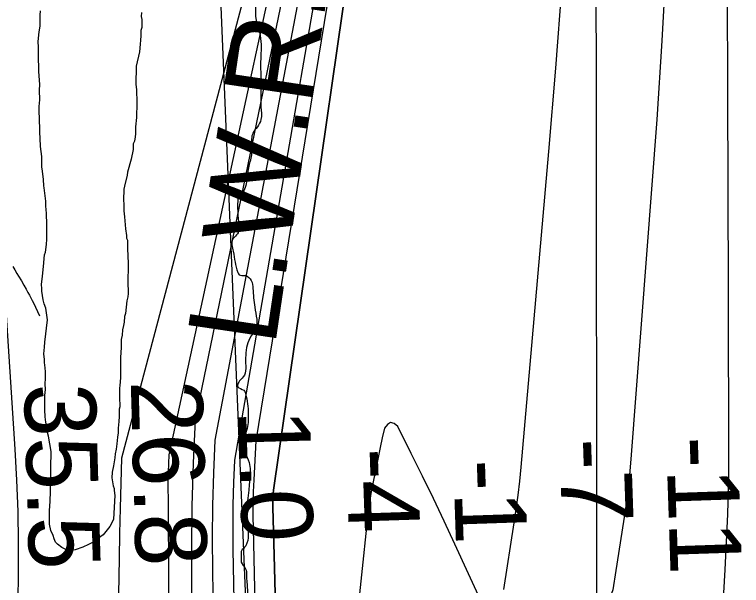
# Model space of a CAD drawing. Extents: x 3313447 to 3351316, y 703786 to 729172.
# Drawn here: x 3322283 to 3322964, y 725253 to 725788 of the extents above; entities that cross this region are included whole.
import ezdxf

# ---------------------------------------------------------------- set-up
doc = ezdxf.new("R2010")
doc.units = 0
for name, color, linetype in [('V-GRID-MAJR', 7, 'Continuous'), ('V-RIVR-EDGE', 7, 'Continuous'), ('V-RIVR-RANG', 7, 'Continuous'), ('V-ROAD-CNTR', 7, 'Continuous'), ('V-RRAP-FSHR', 7, 'Continuous'), ('V-SITE-VEGE', 7, 'Continuous'), ('V-TOPO-DPTH', 7, 'Continuous'), ('V-TOPO-MAJR', 7, 'Continuous'), ('V-TOPO-MINR', 7, 'Continuous'), ('V-TOPO-WATR', 7, 'Continuous'), ('V-TOPO-WATR-IDEN', 7, 'Continuous')]:
    doc.layers.add(name, color=color, linetype=linetype)

msp = doc.modelspace()

# ---------------------------------------------------------------- linework, layer by layer
at = {"layer": 'V-GRID-MAJR'}
msp.add_spline([(3322840.097, 715233.372), (3322833.044, 721295.0380000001), (3322825.991, 727356.734), (3322825.989, 727358.642)], degree=3, dxfattribs=at)
at = {"layer": 'V-RIVR-EDGE'}
msp.add_spline([(3322621.39367418, 727358.3440878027), (3322620.017507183, 727344.96628995), (3322617.494746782, 727330.465586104), (3322616.640161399, 727320.1055978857), (3322620.7439808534, 727303.5160881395), (3322619.4605654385, 727287.3543835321), (3322619.8156031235, 727263.3134304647), (3322623.0412646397, 727226.8308575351), (3322631.523999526, 727137.2813263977), (3322631.0326509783, 727106.1962372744), (3322631.78167231, 727073.8646289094), (3322633.7710635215, 727040.2865013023), (3322632.837561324, 726998.0114360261), (3322629.425369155, 726959.0583722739), (3322631.0146273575, 726931.2840108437), (3322631.385038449, 726913.4602805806), (3322630.5058556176, 726893.1527358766), (3322630.0257809, 726866.6269434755), (3322631.585317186, 726826.832617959), (3322632.7324217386, 726787.8682803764), (3322631.8306912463, 726758.4421422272), (3322628.8381050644, 726721.5604611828), (3322624.2439619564, 726707.4793633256), (3322616.3124439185, 726684.7023526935), (3322612.969944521, 726673.9340323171), (3322610.4502588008, 726660.6767730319), (3322609.184266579, 726651.5612542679), (3322610.3508441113, 726620.4720655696), (3322608.515611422, 726548.7708621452), (3322601.30954216, 726484.1291681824), (3322595.0103278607, 726450.9860199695), (3322590.8245169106, 726434.4170080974), (3322587.496366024, 726429.4514290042), (3322580.435831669, 726423.666110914), (3322577.5242120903, 726419.5284699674), (3322577.102556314, 726416.62812422), (3322577.0892326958, 726411.2398644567), (3322579.968055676, 726402.1140967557), (3322579.100146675, 726386.3658487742), (3322569.100320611, 726365.2518886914), (3322564.5051526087, 726350.756309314), (3322557.812979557, 726326.3182979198), (3322551.9425952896, 726298.9768660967), (3322541.9161219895, 726267.0863864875), (3322531.475167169, 726235.1969317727), (3322515.200724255, 726190.8873799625), (3322507.239484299, 726156.0904052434), (3322503.4199848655, 726120.0397370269), (3322504.1444087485, 726077.7605721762), (3322502.421914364, 726051.6523359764), (3322495.2886125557, 726016.43882995), (3322494.4360769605, 726006.9078047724), (3322495.1943223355, 725978.3065300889), (3322498.8201168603, 725936.0201909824), (3322500.818732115, 725906.1723970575), (3322498.3205691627, 725901.6192496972), (3322497.879440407, 725890.843755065), (3322497.4096146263, 725868.4627778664), (3322499.048067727, 725860.5835294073), (3322502.748679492, 725848.5543412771), (3322506.036859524, 725837.3551410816), (3322506.012262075, 725827.4075845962), (3322505.579332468, 725819.9479421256), (3322505.98049037, 725814.5586574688), (3322509.2748197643, 725805.8463463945), (3322509.26252104, 725800.8725681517), (3322508.4140850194, 725792.999469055), (3322508.8060188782, 725783.8798507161), (3322512.0900993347, 725771.0227244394), (3322513.7193283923, 725759.413142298), (3322513.2659009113, 725743.6638694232), (3322513.6322124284, 725724.1822130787), (3322513.5748183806, 725700.971247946), (3322513.546121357, 725689.3657653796), (3322510.2128460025, 725682.3277786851), (3322506.053682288, 725676.5352863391), (3322504.79691411, 725671.1501012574), (3322504.7641175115, 725657.88669261), (3322502.246481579, 725645.4583963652), (3322500.142302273, 725632.6145937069), (3322495.5512338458, 725619.7769404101), (3322492.6426889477, 725616.8827440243), (3322491.8045018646, 725613.1544601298), (3322492.567871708, 725586.6255930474), (3322492.145191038, 725583.3107657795), (3322488.8190899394, 725579.1741497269), (3322487.15603939, 725577.1058417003), (3322487.5428487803, 725565.9138157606), (3322492.0529506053, 725546.0074289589), (3322493.291270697, 725543.9319466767), (3322498.677480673, 725543.0896600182), (3322504.468948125, 725538.5160147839), (3322506.1084261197, 725531.0512478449), (3322507.7233066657, 725513.6389244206), (3322508.084493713, 725492.0848604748), (3322504.3408364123, 725486.7058247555), (3322500.588979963, 725478.0109368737), (3322499.2973653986, 725458.5333801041), (3322498.03239807, 725449.83234286), (3322493.4597777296, 725444.4553569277), (3322492.2112087, 725442.3860240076), (3322491.7885280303, 725439.0711967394), (3322497.5830701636, 725435.7409960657), (3322499.2327970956, 725432.421044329), (3322501.673566, 725413.7632265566), (3322499.976693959, 725398.0170283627), (3322496.643418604, 725390.9790416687), (3322495.809331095, 725388.9086838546), (3322496.2156134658, 725385.5918067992), (3322498.682004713, 725377.2960270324), (3322502.389790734, 725368.1682095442), (3322503.179807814, 725352.4158619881), (3322500.5924791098, 725311.8028223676), (3322499.2957400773, 725290.2528579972), (3322496.8016767, 725287.3576367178), (3322495.555157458, 725286.1172668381), (3322495.126327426, 725280.3155504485), (3322495.113003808, 725274.9272906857), (3322499.2424456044, 725268.6998189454), (3322500.0560352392, 725262.4805463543), (3322500.852201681, 725249.21508792), (3322500.418247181, 725241.3409639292), (3322499.165578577, 725237.6137049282), (3322496.6684405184, 725233.475039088), (3322496.24063538, 725228.0878042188), (3322496.218087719, 725218.9692107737), (3322496.2088636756, 725215.2388770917), (3322492.455982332, 725206.12950769), (3322492.847916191, 725197.0098893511), (3322495.686768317, 725171.7193423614), (3322501.0135344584, 725146.8371275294), (3322500.974588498, 725131.0868297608), (3322500.922318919, 725109.9482722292), (3322499.2541439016, 725105.8075566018), (3322497.175586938, 725103.325791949), (3322497.168412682, 725100.4244213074), (3322499.1947000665, 725081.7676284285), (3322501.214838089, 725060.6239464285), (3322504.05778979, 725036.9913255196), (3322501.9700087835, 725030.7792271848), (3322500.710165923, 725024.1505975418), (3322501.1041495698, 725015.8599422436), (3322506.0359071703, 724998.8539011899), (3322509.70167255, 724972.7323413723), (3322511.7084869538, 724946.2003996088), (3322509.619681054, 724939.573819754), (3322507.546248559, 724939.1644627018), (3322507.120493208, 724934.6061908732), (3322506.6885884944, 724927.561029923), (3322506.6783395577, 724923.4162147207), (3322510.801631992, 724914.701853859), (3322512.017404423, 724903.5077781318), (3322512.409338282, 724894.3881597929), (3322511.1546198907, 724889.8319377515), (3322507.404813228, 724881.9660129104), (3322507.3966140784, 724878.6501607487), (3322507.798796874, 724873.6753576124), (3322511.099275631, 724867.4499356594), (3322513.565666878, 724859.1541558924), (3322513.1399115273, 724854.5958840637), (3322510.643798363, 724850.8716997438), (3322513.5349200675, 724846.7197102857), (3322517.228357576, 724831.7891515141), (3322520.1266535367, 724830.5385326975), (3322525.070709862, 724818.5062698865), (3322527.088798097, 724796.533624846), (3322526.2598350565, 724796.5356746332), (3322525.8422788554, 724795.2932549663), (3322517.139191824, 724795.729259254), (3322516.7144613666, 724791.5854689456), (3322517.1248433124, 724789.9265179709), (3322525.409349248, 724787.8336124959), (3322527.474582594, 724784.9271173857), (3322529.4895961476, 724761.7110277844), (3322532.3274233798, 724736.0059992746), (3322531.0511822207, 724722.7456653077), (3322528.140587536, 724719.0225058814), (3322527.714832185, 724714.4642340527), (3322529.773916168, 724709.0708498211), (3322531.8422241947, 724707.4077992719), (3322531.8350499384, 724704.5064286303), (3322529.70524829, 724681.3005879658), (3322528.0309239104, 724674.672983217), (3322523.0366477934, 724666.395651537), (3322520.542584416, 724663.5004302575), (3322520.523111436, 724655.6252813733), (3322520.0686590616, 724639.4615269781)], degree=3, dxfattribs=at)
at = {"layer": 'V-ROAD-CNTR'}
msp.add_lwpolyline([(3322281.0474005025, 725551.4958699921), (3322283.061396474, 725548.38187622), (3322285.027392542, 725545.229882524), (3322286.537389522, 725542.7398875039), (3322289.23338413, 725538.1728966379), (3322291.5473795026, 725534.1279047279), (3322293.527375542, 725530.5709118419), (3322295.22837214, 725527.442918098), (3322296.702369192, 725524.6749236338), (3322299.192364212, 725519.879933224), (3322301.030360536, 725516.2379405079), (3322302.392357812, 725513.4819460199), (3322304.381353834, 725509.372954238), (3322306.3043499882, 725505.297962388)], dxfattribs=at)
at = {"layer": 'V-RRAP-FSHR'}
msp.add_lwpolyline([(3322431.258565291, 727358.0675405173), (3322429.6418011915, 726904.7021123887), (3322510.566473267, 724962.8540465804), (3322576.3154653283, 723396.5395491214), (3322621.0663133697, 721565.6439314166)], dxfattribs=at)
at = {"layer": 'V-SITE-VEGE'}
for points in [[(3322314.583, 725392.7930000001), (3322313.387, 725397.343), (3322313.018, 725401.888), (3322312.232, 725406.0210000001), (3322311.452, 725410.981), (3322311.1040000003, 725417.59), (3322311.228, 725430.791), (3322311.6950000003, 725436.5650000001), (3322311.335, 725441.932), (3322311.792, 725446.88), (3322311.8510000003, 725453.069), (3322311.472, 725456.789), (3322310.696, 725461.747), (3322310.723, 725464.637), (3322310.36, 725470.004), (3322310.8310000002, 725476.189), (3322311.286, 725480.726), (3322313.549, 725501.75), (3322312.787, 725508.359), (3322311.9990000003, 725512.4940000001), (3322310.389, 725516.637), (3322309.596, 725520.359), (3322308.437, 725528.622), (3322308.4620000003, 725531.098), (3322308.085, 725534.8150000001), (3322308.984, 725542.649), (3322309.893, 725551.72), (3322310.821, 725562.441), (3322311.669, 725564.909), (3322312.5640000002, 725572.329), (3322313.025, 725577.277), (3322313.156, 725591.305), (3322312.832, 725600.8), (3322312.463, 725605.3420000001), (3322312.074, 725607.822), (3322312.1210000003, 725612.775), (3322310.59, 725625.171), (3322310.194, 725627.238), (3322309.836, 725633.017), (3322309.0840000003, 725640.867), (3322308.298, 725645.002), (3322308.3880000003, 725654.49), (3322307.61, 725659.451), (3322307.239, 725663.993), (3322306.901, 725671.837), (3322306.539, 725677.205), (3322306.27, 725692.4770000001), (3322305.875, 725694.5430000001), (3322305.9450000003, 725701.559), (3322306.416, 725707.7440000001), (3322306.088, 725716.827), (3322306.551, 725722.187), (3322305.427, 725734.166), (3322305.478, 725739.529), (3322305.115, 725744.897), (3322305.228, 725756.866), (3322304.865, 725762.234), (3322305.7770000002, 725771.304), (3322306.653, 725776.66), (3322306.75, 725786.9770000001), (3322307.202, 725791.098)], [(3322401.734, 725789.335), (3322401.244, 725785.671), (3322402.041, 725782.775), (3322401.969, 725775.345), (3322401.117, 725772.4670000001), (3322401.0700000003, 725767.515), (3322400.62, 725763.393), (3322400.583, 725759.68), (3322399.694, 725752.671), (3322396.6750000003, 725739.083), (3322396.515, 725722.162), (3322396.882, 725717.208), (3322397.177, 725704.824), (3322397.048, 725691.207), (3322396.1410000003, 725682.55), (3322396.079, 725675.947), (3322395.639, 725673.064), (3322395.186, 725668.941), (3322393.927, 725666.475), (3322393.876, 725661.111), (3322392.139, 725652.049), (3322388.725, 725640.113), (3322388.284, 725637.23), (3322385.7120000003, 725626.936), (3322385.272, 725624.0530000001), (3322385.2430000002, 725621.1630000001), (3322384.789, 725616.629), (3322384.758, 725613.328), (3322385.143, 725610.434), (3322385.0810000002, 725603.833), (3322385.8510000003, 725598.047), (3322386.572, 725586.898), (3322387.752, 725580.697), (3322387.727, 725578.221), (3322388.532, 725576.15), (3322388.475, 725569.959), (3322388.79, 725559.639), (3322389.171, 725556.336), (3322388.952, 725533.226), (3322389.347, 725531.16), (3322389.3000000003, 725526.208), (3322388.86, 725523.324), (3322388, 725519.617), (3322386.648, 725507.6630000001), (3322385.794, 725504.781), (3322385.333, 725499.422), (3322384.893, 725496.536), (3322384.029, 725492.42), (3322383.5700000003, 725487.4720000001), (3322382.7060000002, 725483.351), (3322382.636, 725475.925), (3322382.132, 725466.439), (3322381.9560000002, 725447.87), (3322381.473, 725440.032), (3322381.039, 725437.974), (3322380.994, 725433.433), (3322380.961, 725429.72), (3322381.282, 725420.226), (3322380.85, 725418.165), (3322380.785, 725411.1510000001), (3322380.33, 725406.617), (3322379.859, 725400.43), (3322379.816, 725395.8910000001), (3322379.363, 725391.769), (3322378.481, 725385.588), (3322378.022, 725380.642), (3322377.154, 725376.11), (3322376.705, 725372.399), (3322375.396, 725364.983), (3322374.1040000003, 725359.218), (3322374.055, 725353.8520000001), (3322374.432, 725350.133), (3322375.222, 725346.414), (3322376.023, 725343.93), (3322376.005, 725341.865), (3322376.787, 725337.319), (3322375.3370000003, 725315.049), (3322374.073, 725312.171), (3322371.97, 725308.0650000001), (3322365.707, 725300.283), (3322360.305, 725296.207), (3322357.808, 725294.167), (3322352.004, 725291.333), (3322346.616, 725288.908), (3322339.579, 725286.495), (3322332.972, 725286.147), (3322330.093, 725287.001), (3322327.217, 725288.679), (3322323.119, 725291.605), (3322321.075, 725293.6900000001), (3322319.865, 725296.59), (3322319.0700000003, 725299.898), (3322316.637, 725304.46), (3322315.454, 725310.248), (3322315.574, 725323.042), (3322316.0700000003, 725331.703), (3322316.107, 725335.416), (3322316.537, 725337.476), (3322316.779, 725363.06), (3322316.9220000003, 725378.328), (3322314.583, 725392.7930000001)]]:
    msp.add_lwpolyline(points, dxfattribs=at)
at = {"layer": 'V-TOPO-DPTH'}
for points in [[(3322446.291441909, 727060.2165192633), (3322610.1736339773, 726161.0959380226), (3322611.769506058, 726142.198720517), (3322612.8079542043, 726123.2832341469), (3322613.010266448, 726104.34034448), (3322612.6551547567, 726085.3791859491), (3322488.6743743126, 725370.4509089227), (3322487.8078002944, 725349.5118847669), (3322487.239951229, 725328.567957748), (3322487.120189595, 725307.6166764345), (3322487.2991529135, 725286.6604922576), (3322496.824701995, 724791.5408622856), (3322497.65556152, 724747.7092945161), (3322498.4698789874, 724703.877424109), (3322499.259383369, 724660.0450997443)], [(3322549.8561720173, 724561.8557197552), (3322528.801114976, 725184.9950225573), (3322528.0144552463, 725209.1203078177), (3322527.2657592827, 725233.2467263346), (3322526.5740089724, 725257.3748447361), (3322525.920222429, 725281.5040963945), (3322524.7662803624, 725326.0333540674), (3322524.739607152, 725327.8985499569), (3322524.7872572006, 725331.6276512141), (3322524.861580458, 725333.491556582), (3322525.158066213, 725339.2476320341), (3322525.4576978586, 725342.1352699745), (3322629.8986936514, 726067.9340090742), (3322630.48452255, 726095.8799987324), (3322630.331320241, 726123.807257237), (3322629.069571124, 726151.7064190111), (3322627.0687908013, 726179.5868496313), (3322552.420344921, 726993.0845297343)], [(3322549.8561720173, 724561.8557197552), (3322528.801114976, 725184.9950225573), (3322528.0144552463, 725209.1203078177), (3322527.2657592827, 725233.2467263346), (3322526.5740089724, 725257.3748447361), (3322525.920222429, 725281.5040963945), (3322524.7662803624, 725326.0333540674), (3322524.739607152, 725327.8985499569), (3322524.7872572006, 725331.6276512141), (3322524.861580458, 725333.491556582), (3322525.158066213, 725339.2476320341), (3322525.4576978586, 725342.1352699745), (3322629.8986936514, 726067.9340090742), (3322630.48452255, 726095.8799987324), (3322630.331320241, 726123.807257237), (3322629.069571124, 726151.7064190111), (3322627.0687908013, 726179.5868496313), (3322552.420344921, 726993.0845297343)], [(3322887.874169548, 726903.8513096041), (3322889.89827548, 726824.9599733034), (3322891.6393698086, 726746.0631531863), (3322892.9559467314, 726667.1581073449), (3322893.9895120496, 726588.2475776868), (3322898.5060803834, 726154.2689115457), (3322898.5879260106, 726142.9488853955), (3322898.62182155, 726131.6288680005), (3322898.5837919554, 726120.308863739), (3322898.497812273, 726108.9888682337), (3322897.152049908, 725984.0641979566), (3322895.6312455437, 725910.3135355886), (3322893.1433391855, 725836.6050509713), (3322889.2047798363, 725762.9598329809), (3322884.299118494, 725689.3567927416), (3322859.960541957, 725371.3991511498), (3322858.665003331, 725356.6933436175), (3322857.145237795, 725342.0133522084), (3322855.289131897, 725327.3720849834), (3322853.2087990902, 725312.7566338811), (3322846.1585168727, 725266.9941860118), (3322843.2267887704, 725248.8230170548), (3322602.521419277, 724601.5518235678)], [(3322887.874169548, 726903.8513096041), (3322889.89827548, 726824.9599733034), (3322891.6393698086, 726746.0631531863), (3322892.9559467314, 726667.1581073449), (3322893.9895120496, 726588.2475776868), (3322898.5060803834, 726154.2689115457), (3322898.5879260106, 726142.9488853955), (3322898.62182155, 726131.6288680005), (3322898.5837919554, 726120.308863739), (3322898.497812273, 726108.9888682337), (3322897.152049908, 725984.0641979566), (3322895.6312455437, 725910.3135355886), (3322893.1433391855, 725836.6050509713), (3322889.2047798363, 725762.9598329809), (3322884.299118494, 725689.3567927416), (3322859.960541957, 725371.3991511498), (3322858.665003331, 725356.6933436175), (3322857.145237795, 725342.0133522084), (3322855.289131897, 725327.3720849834), (3322853.2087990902, 725312.7566338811), (3322846.1585168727, 725266.9941860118), (3322843.2267887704, 725248.8230170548), (3322602.521419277, 724601.5518235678)]]:
    msp.add_lwpolyline(points, dxfattribs=at)
at = {"layer": 'V-TOPO-MAJR'}
msp.add_lwpolyline([(3322385.913870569, 726960.0035415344), (3322586.535264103, 726128.0091619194), (3322586.836178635, 726122.5280891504), (3322586.894817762, 726117.0390756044), (3322586.7919399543, 726111.5447682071), (3322427.323724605, 725375.2936773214), (3322426.9061696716, 725367.2064972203), (3322426.6041915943, 725359.1162422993), (3322426.4755788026, 725351.0213751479), (3322426.462542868, 725342.9234331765), (3322426.532346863, 725334.8231531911), (3322426.596904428, 725326.7228339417), (3322426.6535923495, 725318.6224557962), (3322426.7050338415, 725310.5220383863), (3322426.898974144, 725277.4529261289), (3322427.0652611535, 725252.8181154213), (3322427.260628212, 725228.1835610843), (3322427.4996153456, 725203.5493913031), (3322427.7676825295, 725178.9154778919), (3322434.455812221, 724610.5595691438)], dxfattribs=at)
at = {"layer": 'V-TOPO-MINR'}
for points in [[(3322392.1409231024, 727358.0106447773), (3322393.996268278, 727284.5016237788), (3322399.858928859, 727081.7961704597), (3322400.8413484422, 727057.3236929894), (3322402.1888085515, 727032.8754405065), (3322404.08382945, 727008.4635255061), (3322406.3438908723, 726984.0758354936), (3322416.4352316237, 726887.0334621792), (3322594.1070643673, 726142.6893276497), (3322594.947337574, 726132.7393853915), (3322595.494114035, 726122.7798239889), (3322595.6006453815, 726112.8058338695), (3322595.413679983, 726102.8222246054), (3322451.9483891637, 725408.1433398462), (3322450.1576227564, 725367.7493655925), (3322448.912173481, 725327.3441046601), (3322448.4846999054, 725286.9219137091), (3322448.6025434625, 725246.4884360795), (3322448.80435065, 725231.0082071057), (3322449.428163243, 725182.8260870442), (3322450.046228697, 725134.6438937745), (3322450.6556734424, 725086.4615906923), (3322451.259371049, 725038.2792144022), (3322456.8528678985, 724588.6395593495)], [(3322454.22347942, 727358.1009424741), (3322448.30788716, 727187.6791849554), (3322447.68851915, 727167.8117505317), (3322447.1627460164, 727147.9421703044), (3322446.7773651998, 727128.0693713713), (3322446.485579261, 727108.1944266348), (3322446.225846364, 727084.8955905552), (3322446.178582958, 727076.6687592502), (3322446.190572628, 727068.4423344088), (3322446.291441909, 727060.2165192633), (3322610.1736339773, 726161.0959380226), (3322611.769506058, 726142.198720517), (3322612.8079542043, 726123.2832341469), (3322613.010266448, 726104.34034448), (3322612.6551547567, 726085.3791859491), (3322488.6743743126, 725370.4509089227), (3322487.8078002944, 725349.5118847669), (3322487.239951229, 725328.567957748), (3322487.120189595, 725307.6166764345), (3322487.2991529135, 725286.6604922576), (3322496.824701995, 724791.5408622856), (3322497.65556152, 724747.7092945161), (3322498.4698789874, 724703.877424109), (3322499.259383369, 724660.0450997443)], [(3322546.840045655, 727358.2356512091), (3322515.456786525, 727073.3401223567), (3322516.2489117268, 727056.5457564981), (3322517.4603237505, 727039.7896380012), (3322519.3006660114, 727023.0908905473), (3322521.5602950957, 727006.4303904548), (3322537.039506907, 726906.4562144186), (3322546.821604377, 726839.7693579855), (3322555.893941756, 726772.9918243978), (3322563.9016389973, 726706.0782750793), (3322618.4799955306, 726170.328661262), (3322620.3382779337, 726146.945242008), (3322621.53425012, 726123.5420468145), (3322621.7367569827, 726100.1091877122), (3322621.2769536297, 726076.656552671), (3322508.689833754, 725388.5029068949), (3322506.807013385, 725351.9183461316), (3322506.347942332, 725340.5443325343), (3322506.0569430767, 725329.1678824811), (3322506.018051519, 725317.7877777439), (3322506.1472317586, 725306.4052365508), (3322518.44068928, 724758.3799058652), (3322519.338764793, 724720.1154977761), (3322520.289765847, 724681.8524600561)], [(3322887.874169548, 726903.8513096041), (3322889.89827548, 726824.9599733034), (3322891.6393698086, 726746.0631531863), (3322892.9559467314, 726667.1581073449), (3322893.9895120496, 726588.2475776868), (3322898.5060803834, 726154.2689115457), (3322898.5879260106, 726142.9488853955), (3322898.62182155, 726131.6288680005), (3322898.5837919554, 726120.308863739), (3322898.497812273, 726108.9888682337), (3322897.152049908, 725984.0641979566), (3322895.6312455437, 725910.3135355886), (3322893.1433391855, 725836.6050509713), (3322889.2047798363, 725762.9598329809), (3322884.299118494, 725689.3567927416), (3322859.960541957, 725371.3991511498), (3322858.665003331, 725356.6933436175), (3322857.145237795, 725342.0133522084), (3322855.289131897, 725327.3720849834), (3322853.2087990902, 725312.7566338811), (3322846.1585168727, 725266.9941860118), (3322843.2267887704, 725248.8230170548), (3322602.521419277, 724601.5518235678)], [(3322443.0617683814, 726894.1580011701), (3322452.3264059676, 726860.204803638), (3322602.139488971, 726151.891560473), (3322603.3574894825, 726137.4685020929), (3322604.150063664, 726123.0315006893), (3322604.3044983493, 726108.5735847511), (3322604.0335067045, 726094.1017257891), (3322470.4055060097, 725389.1686675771), (3322469.0988011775, 725358.5686904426), (3322468.2164311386, 725327.9608940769), (3322467.970563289, 725297.3413688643), (3322468.149030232, 725266.7140244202), (3322470.488588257, 725122.5230649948), (3322472.074881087, 725023.4856322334), (3322473.6336734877, 724924.4477723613), (3322475.1512152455, 724825.4092718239), (3322476.6412565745, 724726.3703441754), (3322479.006972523, 724566.92010775)], [(3322948.840106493, 726105.7032251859), (3322949.8695109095, 725902.7696821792), (3322950.297516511, 725809.4752905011), (3322950.665201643, 725716.1806903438), (3322950.9424060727, 725622.8857774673), (3322951.159290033, 725529.590656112), (3322951.4597032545, 725366.3037667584), (3322951.402050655, 725354.6535779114), (3322951.2389903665, 725343.005580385), (3322950.917818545, 725331.3608698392), (3322950.491239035, 725319.7183506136), (3322948.2236574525, 725267.5169434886), (3322946.0715399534, 725229.8210022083)], [(3322575.26041383, 726097.630221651), (3322383.095388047, 725372.3147367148), (3322382.3362602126, 725348.8168881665), (3322381.6609270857, 725325.3168558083), (3322381.111286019, 725301.8135477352), (3322380.6454396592, 725278.3080558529), (3322377.7700810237, 725110.5857940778), (3322376.23577169, 725013.3340058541), (3322374.8786659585, 724916.0799870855), (3322373.78736563, 724818.8226224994), (3322372.8732689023, 724721.5630273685), (3322371.6876670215, 724573.9511950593)], [(3322812.1973215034, 726091.0429601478), (3322805.575524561, 725972.4027021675), (3322800.8224863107, 725894.0487928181), (3322795.5652008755, 725815.7311800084), (3322789.551544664, 725737.4680120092), (3322783.0336412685, 725659.2411405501), (3322756.987789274, 725363.8922462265), (3322755.6940308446, 725350.7588044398), (3322754.221629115, 725337.6472769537), (3322752.481262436, 725324.5686209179), (3322750.562252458, 725311.5118791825), (3322740.734839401, 725249.0936232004)], [(3322256.6, 725785.73), (3322283.0410125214, 725380.5849383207), (3322284.601698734, 725351.4795123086), (3322285.711962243, 725322.3621408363), (3322286.1465916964, 725293.226851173), (3322286.1307984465, 725264.0796160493), (3322281.16, 724854.71)], [(3322722.6332857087, 725232.1146911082), (3322695.063837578, 725291.7968156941), (3322685.1230441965, 725313.0733351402), (3322675.0596329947, 725334.2910440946), (3322664.812295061, 725355.4205373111), (3322654.4423393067, 725376.4912200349), (3322641.8564151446, 725401.7866147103), (3322638.3558098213, 725404.5063064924), (3322635.0637428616, 725405.4602702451), (3322632.0844834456, 725403.7656419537), (3322629.313762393, 725400.3052856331), (3322627.251015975, 725391.177220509), (3322625.241069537, 725382.0377829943), (3322623.3103230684, 725372.8812868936), (3322621.4323765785, 725363.7134184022), (3322617.7792405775, 725345.4781402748), (3322616.577249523, 725339.0112095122), (3322615.4960803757, 725332.5258639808), (3322614.596144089, 725326.0128962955), (3322613.81702971, 725319.4815138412), (3322594.121525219, 725132.2014461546)]]:
    msp.add_lwpolyline(points, dxfattribs=at)
at = {"layer": 'V-TOPO-WATR'}
msp.add_lwpolyline([(3322552.420344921, 726993.0845297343), (3322627.0687908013, 726179.5868496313), (3322629.069571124, 726151.7064190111), (3322630.331320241, 726123.807257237), (3322630.48452255, 726095.8799987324), (3322629.8986936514, 726067.9340090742), (3322525.4576978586, 725342.1352699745), (3322525.158066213, 725339.2476320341), (3322524.861580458, 725333.491556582), (3322524.7872572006, 725331.6276512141), (3322524.739607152, 725327.8985499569), (3322524.7662803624, 725326.0333540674), (3322525.920222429, 725281.5040963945), (3322526.5740089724, 725257.3748447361), (3322527.2657592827, 725233.2467263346), (3322528.0144552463, 725209.1203078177), (3322528.801114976, 725184.9950225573), (3322549.8561720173, 724561.8557197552)], dxfattribs=at)

# ---------------------------------------------------------------- texts
at = {"layer": 'V-RIVR-RANG'}
for s, height, rotation, p in [('26.8', 67, 271.6383257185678, (3322391.5710053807, 725444.4774897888)), ('35.5', 67, 271.6383257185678, (3322291.6190053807, 725441.3784897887)), ('1.0', 66.99999999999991, 271.6383257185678, (3322492.3902814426, 725417.2532444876)), ('-7', 67.00000000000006, 271.9173333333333, (3322793.038149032, 725389.9916466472)), ('-11', 67.00000000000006, 271.9173333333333, (3322893.0342760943, 725391.7724874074)), ('-4', 67.00000000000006, 271.9173333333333, (3322593.23122857, 725380.8946963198)), ('-1', 67.00000000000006, 271.9173333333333, (3322693.6421500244, 725370.2848402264))]:
    msp.add_text(s, height=height, rotation=rotation, dxfattribs=at).set_placement(p)
at = {"layer": 'V-TOPO-WATR-IDEN'}
msp.add_text('L.W.R.P.', height=83, rotation=81.54993663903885, dxfattribs=at).set_placement((3322526.5402120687, 725475.556564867))

doc.saveas('drawing.dxf')
